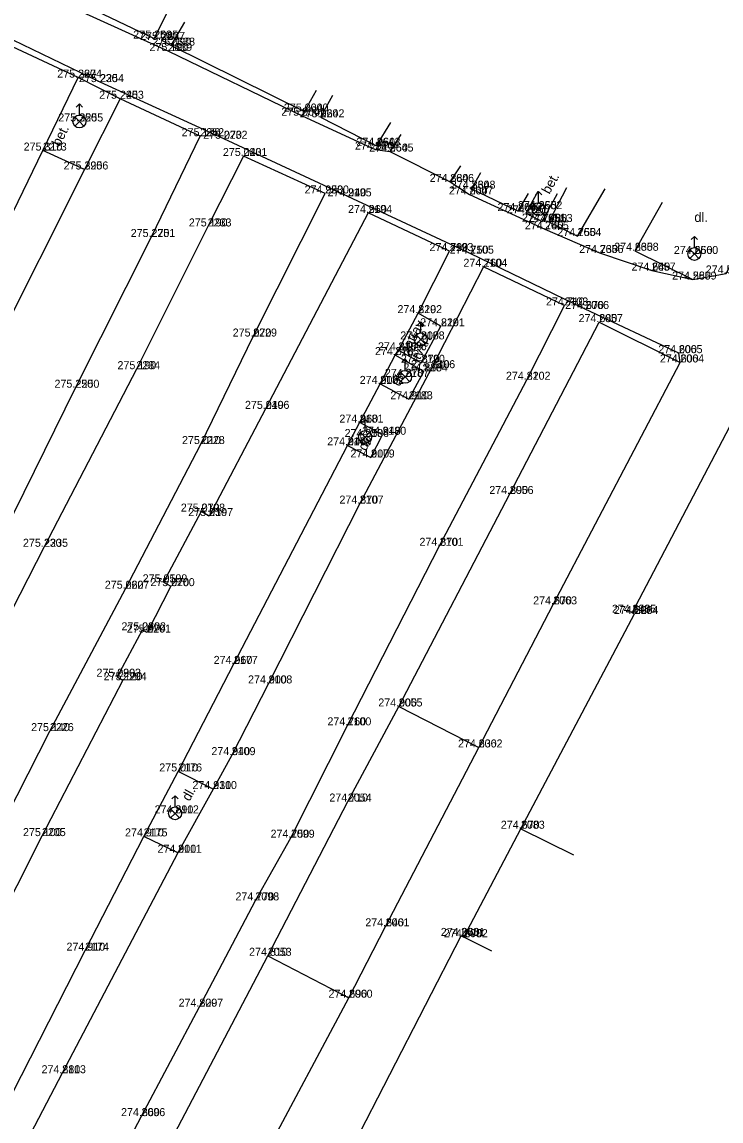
# Model space of a CAD drawing. Extents: x -776701 to -776081, y -974398 to -973771.
# Drawn here: x -776412.71 to -776390.87, y -974168.17 to -974133.83 of the extents above; entities that cross this region are included whole.
import ezdxf

# ---------------------------------------------------------------- set-up
doc = ezdxf.new("R2010")
doc.units = 0
for name, color, linetype in [('1 Body-bod', 7, 'Continuous'), ('10 Silnice-chodniky', 7, 'Continuous'), ('11 Rozhrani-nezpev zpev schody', 7, 'Continuous'), ('2 Body-cislo', 7, 'Continuous'), ('3 Body-vyska', 7, 'Continuous'), ('40 Popis-povrch', 7, 'Continuous'), ('58 Mobiliar', 7, 'Continuous'), ('7 Ploty', 7, 'Continuous')]:
    doc.layers.add(name, color=color, linetype=linetype)

msp = doc.modelspace()

# ---------------------------------------------------------------- linework, layer by layer
at = {"layer": '1 Body-bod'}
for p, q in [((-776408.58, -974134.35), (-776408.58, -974134.35)), ((-776408.36, -974134.39), (-776408.36, -974134.39)), ((-776408.05, -974134.57), (-776408.05, -974134.57)), ((-776408.14, -974134.74), (-776408.14, -974134.74)), ((-776410.96, -974135.57), (-776410.96, -974135.57)), ((-776410.27, -974135.71), (-776410.27, -974135.71)), ((-776409.65, -974136.23), (-776409.65, -974136.23)), ((-776403.88, -974136.63), (-776403.88, -974136.63)), ((-776410.92, -974136.94), (-776410.92, -974136.94)), ((-776403.96, -974136.76), (-776403.96, -974136.76)), ((-776403.38, -974136.81), (-776403.38, -974136.81)), ((-776407.14, -974137.4), (-776407.14, -974137.4)), ((-776406.41, -974137.48), (-776406.41, -974137.48)), ((-776401.63, -974137.7), (-776401.63, -974137.7)), ((-776412.06, -974137.85), (-776412.06, -974137.85)), ((-776405.79, -974138.02), (-776405.79, -974138.02)), ((-776401.68, -974137.82), (-776401.68, -974137.82)), ((-776401.22, -974137.88), (-776401.22, -974137.88)), ((-776410.76, -974138.44), (-776410.76, -974138.44)), ((-776399.33, -974138.83), (-776399.33, -974138.83)), ((-776398.66, -974139.04), (-776398.66, -974139.04)), ((-776403.24, -974139.19), (-776403.24, -974139.19)), ((-776402.53, -974139.28), (-776402.53, -974139.28)), ((-776398.73, -974139.22), (-776398.73, -974139.22)), ((-776397.21, -974139.74), (-776397.21, -974139.74)), ((-776396.57, -974139.68), (-776396.57, -974139.68)), ((-776401.89, -974139.8), (-776401.89, -974139.8)), ((-776396.97, -974139.81), (-776396.97, -974139.81)), ((-776396.46, -974140.07), (-776396.46, -974140.07)), ((-776396.25, -974140.08), (-776396.25, -974140.08)), ((-776406.91, -974140.22), (-776406.91, -974140.22)), ((-776396.37, -974140.31), (-776396.37, -974140.31)), ((-776408.67, -974140.55), (-776408.67, -974140.55)), ((-776395.35, -974140.52), (-776395.35, -974140.52)), ((-776399.35, -974140.99), (-776399.35, -974140.99)), ((-776398.71, -974141.07), (-776398.71, -974141.07)), ((-776394.66, -974141.05), (-776394.66, -974141.05)), ((-776393.56, -974140.98), (-776393.56, -974140.98)), ((-776391.7, -974141.08), (-776391.7, -974141.08)), ((-776398.29, -974141.48), (-776398.29, -974141.48)), ((-776393.03, -974141.6), (-776393.03, -974141.6)), ((-776391.75, -974141.88), (-776391.75, -974141.88)), ((-776395.76, -974142.69), (-776395.76, -974142.69)), ((-776395.11, -974142.8), (-776395.11, -974142.8)), ((-776400.33, -974142.93), (-776400.33, -974142.93)), ((-776399.62, -974143.34), (-776399.62, -974143.34)), ((-776394.68, -974143.21), (-776394.68, -974143.21)), ((-776405.49, -974143.66), (-776405.49, -974143.66)), ((-776400.25, -974143.75), (-776400.25, -974143.75)), ((-776400.95, -974144.09), (-776400.95, -974144.09)), ((-776392.19, -974144.18), (-776392.19, -974144.18)), ((-776401.05, -974144.24), (-776401.05, -974144.24)), ((-776400.24, -974144.48), (-776400.24, -974144.48)), ((-776392.14, -974144.47), (-776392.14, -974144.47)), ((-776409.14, -974144.68), (-776409.14, -974144.68)), ((-776400.74, -974144.92), (-776400.74, -974144.92)), ((-776400.15, -974144.75), (-776400.15, -974144.75)), ((-776399.92, -974144.65), (-776399.92, -974144.65)), ((-776411.04, -974145.26), (-776411.04, -974145.26)), ((-776401.52, -974145.14), (-776401.52, -974145.14)), ((-776396.94, -974145.01), (-776396.94, -974145.01)), ((-776405.1, -974145.92), (-776405.1, -974145.92)), ((-776400.62, -974145.62), (-776400.62, -974145.62)), ((-776402.16, -974146.35), (-776402.16, -974146.35)), ((-776401.99, -974146.8), (-776401.99, -974146.8)), ((-776401.45, -974146.73), (-776401.45, -974146.73)), ((-776407.12, -974147.02), (-776407.12, -974147.02)), ((-776402.54, -974147.06), (-776402.54, -974147.06)), ((-776401.81, -974147.44), (-776401.81, -974147.44)), ((-776397.47, -974148.58), (-776397.47, -974148.58)), ((-776402.16, -974148.88), (-776402.16, -974148.88)), ((-776407.11, -974149.13), (-776407.11, -974149.13)), ((-776406.86, -974149.27), (-776406.86, -974149.27)), ((-776412.02, -974150.23), (-776412.02, -974150.23)), ((-776399.66, -974150.2), (-776399.66, -974150.2)), ((-776408.29, -974151.34), (-776408.29, -974151.34)), ((-776409.48, -974151.54), (-776409.48, -974151.54)), ((-776408.06, -974151.46), (-776408.06, -974151.46)), ((-776396.11, -974152.03), (-776396.11, -974152.03)), ((-776393.64, -974152.29), (-776393.64, -974152.29)), ((-776393.57, -974152.33), (-776393.57, -974152.33)), ((-776408.96, -974152.84), (-776408.96, -974152.84)), ((-776408.8, -974152.91), (-776408.8, -974152.91)), ((-776406.09, -974153.89), (-776406.09, -974153.89)), ((-776409.74, -974154.29), (-776409.74, -974154.29)), ((-776409.56, -974154.4), (-776409.56, -974154.4)), ((-776405.01, -974154.5), (-776405.01, -974154.5)), ((-776400.94, -974155.22), (-776400.94, -974155.22)), ((-776402.54, -974155.81), (-776402.54, -974155.81)), ((-776411.84, -974155.99), (-776411.84, -974155.99)), ((-776398.44, -974156.5), (-776398.44, -974156.5)), ((-776406.16, -974156.74), (-776406.16, -974156.74)), ((-776407.83, -974157.25), (-776407.83, -974157.25)), ((-776406.74, -974157.8), (-776406.74, -974157.8)), ((-776402.53, -974158.19), (-776402.53, -974158.19)), ((-776407.93, -974158.56), (-776407.93, -974158.56)), ((-776412.09, -974159.27), (-776412.09, -974159.27)), ((-776408.91, -974159.28), (-776408.91, -974159.28)), ((-776404.31, -974159.32), (-776404.31, -974159.32)), ((-776397.12, -974159.04), (-776397.12, -974159.04)), ((-776407.84, -974159.79), (-776407.84, -974159.79)), ((-776405.42, -974161.28), (-776405.42, -974161.28)), ((-776401.35, -974162.09), (-776401.35, -974162.09)), ((-776398.99, -974162.39), (-776398.99, -974162.39)), ((-776398.9, -974162.43), (-776398.9, -974162.43)), ((-776410.74, -974162.85), (-776410.74, -974162.85)), ((-776405.03, -974163.01), (-776405.03, -974163.01)), ((-776402.5, -974164.32), (-776402.5, -974164.32)), ((-776407.17, -974164.6), (-776407.17, -974164.6)), ((-776411.46, -974166.68), (-776411.46, -974166.68)), ((-776408.98, -974168.02), (-776408.98, -974168.02))]:
    msp.add_line(p, q, dxfattribs=at)
at = {"layer": '10 Silnice-chodniky'}
for points in [[(-776398.71, -974141.07), (-776402.53, -974139.28), (-776406.41, -974137.48), (-776410.27, -974135.71), (-776414.21, -974133.82), (-776417.97, -974132.05), (-776421.8, -974130.27), (-776425.67, -974128.29), (-776429.7, -974126.41), (-776433.28, -974124.7), (-776436.96, -974123), (-776442.03, -974120.71), (-776442.3, -974120.97)], [(-776432.81, -974123), (-776431.7, -974123.4), (-776424.58, -974126.72), (-776422.72, -974127.77), (-776420.37, -974128.93), (-776419.95, -974129.14), (-776417.98, -974130.1), (-776417.46, -974130.35), (-776415.61, -974131.25), (-776413.4, -974132.37), (-776410.5, -974133.67), (-776408.14, -974134.74), (-776403.96, -974136.76), (-776401.68, -974137.82), (-776401.22, -974137.88)], [(-776409.65, -974136.23), (-776410.96, -974135.57)], [(-776410.76, -974138.44), (-776412.06, -974137.85)], [(-776399.33, -974138.83), (-776398.73, -974139.22), (-776396.37, -974140.31), (-776394.66, -974141.05), (-776393.03, -974141.6), (-776391.75, -974141.88)], [(-776396.597, -974139.131), (-776396.97, -974139.81), (-776396.46, -974140.07), (-776395.982, -974139.196)], [(-776392.14, -974144.47), (-776392.19, -974144.18), (-776395.11, -974142.8), (-776398.71, -974141.07)], [(-776400.95, -974144.09), (-776400.24, -974144.48), (-776399.62, -974143.34), (-776400.33, -974142.93)], [(-776401.52, -974145.14), (-776400.62, -974145.62), (-776400.15, -974144.75), (-776401.05, -974144.24)], [(-776402.54, -974147.06), (-776401.81, -974147.44), (-776401.45, -974146.73), (-776402.16, -974146.35)], [(-776397.12, -974159.04), (-776393.57, -974152.33)], [(-776406.74, -974157.8), (-776407.83, -974157.25)], [(-776407.84, -974159.79), (-776408.91, -974159.28)], [(-776400.67, -974169.754), (-776402.33, -974168.89), (-776398.99, -974162.39), (-776398.9, -974162.43)]]:
    msp.add_lwpolyline(points, dxfattribs=at)
at = {"layer": '11 Rozhrani-nezpev zpev schody'}
msp.add_lwpolyline([(-776392.71, -974139.472), (-776393.56, -974140.98), (-776391.75, -974141.88), (-776390.71, -974141.69), (-776389.38, -974139.19), (-776387.61, -974135.82), (-776388.963, -974135.076)], dxfattribs=at)
at = {"layer": '58 Mobiliar'}
for p, q in [((-776410.92, -974136.39), (-776411.02, -974136.49)), ((-776410.92, -974136.738), (-776410.92, -974136.39)), ((-776410.92, -974136.39), (-776410.82, -974136.49)), ((-776410.92, -974136.94), (-776411.062, -974136.797)), ((-776410.92, -974136.94), (-776411.062, -974137.083)), ((-776410.92, -974136.94), (-776410.777, -974136.797)), ((-776410.92, -974136.94), (-776410.92, -974136.94)), ((-776410.92, -974136.94), (-776410.777, -974137.083)), ((-776396.57, -974139.13), (-776396.67, -974139.23)), ((-776396.57, -974139.478), (-776396.57, -974139.13)), ((-776396.57, -974139.13), (-776396.47, -974139.23)), ((-776396.57, -974139.68), (-776396.713, -974139.537)), ((-776396.57, -974139.68), (-776396.713, -974139.823)), ((-776396.57, -974139.68), (-776396.427, -974139.537)), ((-776396.57, -974139.68), (-776396.57, -974139.68)), ((-776396.57, -974139.68), (-776396.427, -974139.823)), ((-776391.7, -974140.53), (-776391.8, -974140.63)), ((-776391.7, -974140.878), (-776391.7, -974140.53)), ((-776391.7, -974140.53), (-776391.6, -974140.63)), ((-776391.7, -974141.08), (-776391.843, -974140.938)), ((-776391.7, -974141.08), (-776391.843, -974141.223)), ((-776391.7, -974141.08), (-776391.557, -974140.938)), ((-776391.7, -974141.08), (-776391.7, -974141.08)), ((-776391.7, -974141.08), (-776391.557, -974141.223)), ((-776400.25, -974143.2), (-776400.35, -974143.3)), ((-776400.25, -974143.549), (-776400.25, -974143.2)), ((-776400.25, -974143.2), (-776400.15, -974143.3)), ((-776400.25, -974143.75), (-776400.392, -974143.608)), ((-776400.25, -974143.75), (-776400.392, -974143.893)), ((-776400.25, -974143.75), (-776400.108, -974143.608)), ((-776400.25, -974143.75), (-776400.25, -974143.75)), ((-776400.25, -974143.75), (-776400.108, -974143.893)), ((-776400.74, -974144.37), (-776400.84, -974144.47)), ((-776400.74, -974144.719), (-776400.74, -974144.37)), ((-776400.74, -974144.37), (-776400.64, -974144.47)), ((-776400.74, -974144.92), (-776400.883, -974144.777)), ((-776400.74, -974144.92), (-776400.883, -974145.062)), ((-776400.74, -974144.92), (-776400.598, -974144.777)), ((-776400.74, -974144.92), (-776400.74, -974144.92)), ((-776400.74, -974144.92), (-776400.598, -974145.062)), ((-776401.99, -974146.25), (-776402.09, -974146.35)), ((-776401.99, -974146.598), (-776401.99, -974146.25)), ((-776401.99, -974146.25), (-776401.89, -974146.35)), ((-776401.99, -974146.8), (-776402.133, -974146.657)), ((-776401.99, -974146.8), (-776402.133, -974146.943)), ((-776401.99, -974146.8), (-776401.848, -974146.657)), ((-776401.99, -974146.8), (-776401.99, -974146.8)), ((-776401.99, -974146.8), (-776401.848, -974146.943)), ((-776407.93, -974158.01), (-776408.03, -974158.11)), ((-776407.93, -974158.358), (-776407.93, -974158.01)), ((-776407.93, -974158.01), (-776407.83, -974158.11)), ((-776407.93, -974158.56), (-776408.073, -974158.417)), ((-776407.93, -974158.56), (-776408.073, -974158.703)), ((-776407.93, -974158.56), (-776407.787, -974158.417)), ((-776407.93, -974158.56), (-776407.93, -974158.56)), ((-776407.93, -974158.56), (-776407.787, -974158.703))]:
    msp.add_line(p, q, dxfattribs=at)
for centre in [(-776410.92, -974136.94), (-776396.57, -974139.68), (-776391.7, -974141.08), (-776400.25, -974143.75), (-776400.74, -974144.92), (-776401.99, -974146.8), (-776407.93, -974158.56)]:
    msp.add_circle(centre, 0.202, dxfattribs=at)
at = {"layer": '7 Ploty'}
for p, q in [((-776408.05, -974134.57), (-776407.62, -974133.839)), ((-776400.94, -974155.22), (-776398.44, -974156.5)), ((-776405.03, -974163.01), (-776402.5, -974164.32))]:
    msp.add_line(p, q, dxfattribs=at)
for points in [[(-776409.898, -974132.463), (-776410.4, -974133.48), (-776408.58, -974134.35), (-776408.099, -974133.401)], [(-776432.01, -974176.96), (-776430.15, -974174.43), (-776428.84, -974172.48), (-776426.21, -974167.13), (-776424.02, -974162.64), (-776420.72, -974155.89), (-776417.48, -974149.18), (-776414.84, -974143.58), (-776412.06, -974137.85), (-776410.96, -974135.57), (-776413.49, -974134.39), (-776415.66, -974138.85), (-776417.85, -974143.38), (-776420.08, -974148.01), (-776422.17, -974152.39), (-776424.4, -974156.87), (-776426.57, -974161.43), (-776428.76, -974165.89), (-776429.88, -974168.2), (-776431.18, -974170.86), (-776433.91, -974174.88), (-776432.01, -974176.96)], [(-776408.36, -974134.39), (-776408.05, -974134.57), (-776403.88, -974136.63), (-776403.514, -974135.965)], [(-776431.34, -974177.69), (-776430.36, -974178.74), (-776429.05, -974179.3), (-776425.05, -974173.32), (-776421.66, -974166.59), (-776420.59, -974164.45), (-776417.2, -974157.6), (-776414.58, -974152.44), (-776411.04, -974145.26), (-776408.67, -974140.55), (-776407.14, -974137.4), (-776409.65, -974136.23), (-776410.76, -974138.44), (-776413.59, -974144.07), (-776416.31, -974149.56), (-776419.81, -974156.48), (-776423.16, -974163.16), (-776425.35, -974167.56), (-776426.48, -974169.85), (-776427.57, -974172.05), (-776429.18, -974174.63), (-776431.34, -974177.69)], [(-776403.009, -974136.124), (-776403.38, -974136.81), (-776401.63, -974137.7), (-776401.186, -974136.974)], [(-776400.875, -974137.35), (-776401.22, -974137.88), (-776399.33, -974138.83), (-776398.998, -974138.324)], [(-776418.01, -974168.03), (-776415.29, -974162.66), (-776413.55, -974159.33), (-776411.84, -974155.99), (-776409.48, -974151.54), (-776407.12, -974147.02), (-776405.49, -974143.66), (-776403.24, -974139.19), (-776405.79, -974138.02), (-776406.91, -974140.22), (-776409.14, -974144.68), (-776412.02, -974150.23), (-776414.31, -974154.7), (-776417.77, -974161.35), (-776420.5, -974166.71), (-776418.01, -974168.03)], [(-776398.389, -974138.549), (-776398.66, -974139.04), (-776397.21, -974139.74), (-776396.881, -974139.19)], [(-776395.692, -974139.012), (-776396.25, -974140.08), (-776395.35, -974140.52), (-776394.486, -974139.042)], [(-776414.17, -974169.55), (-776410.74, -974162.85), (-776408.91, -974159.28), (-776407.83, -974157.25), (-776406.09, -974153.89), (-776402.54, -974147.06), (-776401.52, -974145.14), (-776401.05, -974144.24), (-776400.95, -974144.09), (-776400.33, -974142.93), (-776399.35, -974140.99), (-776401.89, -974139.8), (-776405.1, -974145.92), (-776406.86, -974149.27), (-776407.11, -974149.13), (-776408.29, -974151.34), (-776408.06, -974151.46), (-776408.8, -974152.91), (-776408.96, -974152.84), (-776409.74, -974154.29), (-776409.56, -974154.4), (-776412.09, -974159.27), (-776414.44, -974163.91)], [(-776413.04, -974175.78), (-776408.98, -974168.02), (-776407.17, -974164.6), (-776405.42, -974161.28), (-776404.31, -974159.32), (-776402.54, -974155.81), (-776399.66, -974150.2), (-776396.94, -974145.01), (-776395.76, -974142.69), (-776398.29, -974141.48), (-776399.92, -974144.65), (-776402.16, -974148.88), (-776405.01, -974154.5), (-776406.16, -974156.74), (-776406.74, -974157.8), (-776407.84, -974159.79), (-776411.46, -974166.68), (-776415.53, -974174.46)], [(-776410.02, -974178.63), (-776411.75, -974182.02), (-776414.07, -974185.17), (-776414.88, -974186.15), (-776415.02, -974186.06), (-776417.11, -974188.76), (-776419.58, -974186.86), (-776418.35, -974185.27), (-776418.07, -974185.5), (-776417.25, -974184.38), (-776417.17, -974184.42), (-776416.48, -974183.46), (-776415.65, -974182.42), (-776415.01, -974181.59), (-776414.32, -974180.57), (-776411.96, -974176.29), (-776407.95, -974168.57), (-776405.03, -974163.01), (-776402.53, -974158.19), (-776400.94, -974155.22), (-776397.47, -974148.58), (-776394.68, -974143.21), (-776392.14, -974144.47)], [(-776410.02, -974178.63), (-776408, -974174.76), (-776405.13, -974169.26), (-776402.5, -974164.32), (-776401.35, -974162.09), (-776398.44, -974156.5), (-776396.11, -974152.03), (-776392.14, -974144.47)], [(-776393.57, -974152.33), (-776393.64, -974152.29), (-776390.14, -974145.62)], [(-776398.025, -974162.863), (-776398.9, -974162.43), (-776397.12, -974159.04), (-776395.475, -974159.855)]]:
    msp.add_lwpolyline(points, dxfattribs=at)

# ---------------------------------------------------------------- texts
at = {"layer": '2 Body-cislo'}
for s, p in [('2635', (-776408.58, -974134.35)), ('2637', (-776408.36, -974134.39)), ('2639', (-776408.14, -974134.74)), ('2638', (-776408.05, -974134.57)), ('2274', (-776410.96, -974135.57)), ('2254', (-776410.27, -974135.71)), ('2253', (-776409.65, -974136.23)), ('2641', (-776403.96, -974136.76)), ('2640', (-776403.88, -974136.63)), ('2642', (-776403.38, -974136.81)), ('2255', (-776410.92, -974136.94)), ('2252', (-776407.14, -974137.4)), ('2232', (-776406.41, -974137.48)), ('2273', (-776412.06, -974137.85)), ('2644', (-776401.68, -974137.82)), ('2643', (-776401.63, -974137.7)), ('2645', (-776401.22, -974137.88)), ('2231', (-776405.79, -974138.02)), ('2256', (-776410.76, -974138.44)), ('2646', (-776399.33, -974138.83)), ('2230', (-776403.24, -974139.19)), ('2195', (-776402.53, -974139.28)), ('2647', (-776398.73, -974139.22)), ('2648', (-776398.66, -974139.04)), ('2652', (-776396.57, -974139.68)), ('2194', (-776401.89, -974139.8)), ('2649', (-776397.21, -974139.74)), ('2650', (-776396.97, -974139.81)), ('2233', (-776406.91, -974140.22)), ('2651', (-776396.46, -974140.07)), ('2655', (-776396.37, -974140.31)), ('2653', (-776396.25, -974140.08)), ('2251', (-776408.67, -974140.55)), ('2654', (-776395.35, -974140.52)), ('2193', (-776399.35, -974140.99)), ('2656', (-776394.66, -974141.05)), ('2658', (-776393.56, -974140.98)), ('2105', (-776398.71, -974141.07)), ('2660', (-776391.7, -974141.08)), ('2104', (-776398.29, -974141.48)), ('2657', (-776393.03, -974141.6)), ('2659', (-776391.75, -974141.88)), ('2103', (-776395.76, -974142.69)), ('2192', (-776400.33, -974142.93)), ('2066', (-776395.11, -974142.8)), ('2191', (-776399.62, -974143.34)), ('2057', (-776394.68, -974143.21)), ('2229', (-776405.49, -974143.66)), ('2188', (-776400.25, -974143.75)), ('2189', (-776400.95, -974144.09)), ('2185', (-776401.05, -974144.24)), ('2190', (-776400.24, -974144.48)), ('2065', (-776392.19, -974144.18)), ('2064', (-776392.14, -974144.47)), ('2234', (-776409.14, -974144.68)), ('2184', (-776400.15, -974144.75)), ('2106', (-776399.92, -974144.65)), ('2182', (-776401.52, -974145.14)), ('2187', (-776400.74, -974144.92)), ('2102', (-776396.94, -974145.01)), ('2250', (-776411.04, -974145.26)), ('2183', (-776400.62, -974145.62)), ('2196', (-776405.1, -974145.92)), ('2181', (-776402.16, -974146.35)), ('2186', (-776401.99, -974146.8)), ('2180', (-776401.45, -974146.73)), ('2228', (-776407.12, -974147.02)), ('2178', (-776402.54, -974147.06)), ('2179', (-776401.81, -974147.44)), ('2056', (-776397.47, -974148.58)), ('2107', (-776402.16, -974148.88)), ('2198', (-776407.11, -974149.13)), ('2197', (-776406.86, -974149.27)), ('2235', (-776412.02, -974150.23)), ('2101', (-776399.66, -974150.2)), ('2199', (-776408.29, -974151.34)), ('2227', (-776409.48, -974151.54)), ('2200', (-776408.06, -974151.46)), ('2063', (-776396.11, -974152.03)), ('2085', (-776393.64, -974152.29)), ('2084', (-776393.57, -974152.33)), ('2202', (-776408.96, -974152.84)), ('2201', (-776408.8, -974152.91)), ('2177', (-776406.09, -974153.89)), ('2203', (-776409.74, -974154.29)), ('2204', (-776409.56, -974154.4)), ('2108', (-776405.01, -974154.5)), ('2055', (-776400.94, -974155.22)), ('2100', (-776402.54, -974155.81)), ('2226', (-776411.84, -974155.99)), ('2062', (-776398.44, -974156.5)), ('2109', (-776406.16, -974156.74)), ('2176', (-776407.83, -974157.25)), ('2110', (-776406.74, -974157.8)), ('2054', (-776402.53, -974158.19)), ('2112', (-776407.93, -974158.56)), ('2083', (-776397.12, -974159.04)), ('2205', (-776412.09, -974159.27)), ('2175', (-776408.91, -974159.28)), ('2099', (-776404.31, -974159.32)), ('2111', (-776407.84, -974159.79)), ('2098', (-776405.42, -974161.28)), ('2061', (-776401.35, -974162.09)), ('2081', (-776398.99, -974162.39)), ('2082', (-776398.9, -974162.43)), ('2174', (-776410.74, -974162.85)), ('2053', (-776405.03, -974163.01)), ('2060', (-776402.5, -974164.32)), ('2097', (-776407.17, -974164.6)), ('2113', (-776411.46, -974166.68)), ('2096', (-776408.98, -974168.02))]:
    msp.add_text(s, height=0.25, dxfattribs=at).set_placement(p)
at = {"layer": '3 Body-vyska'}
for s, p in [('275.250', (-776409.238, -974134.35)), ('275.220', (-776409.022, -974134.39)), ('275.190', (-776408.729, -974134.74)), ('275.190', (-776408.639, -974134.57)), ('275.260', (-776411.612, -974135.57)), ('275.230', (-776410.934, -974135.71)), ('275.240', (-776410.302, -974136.23)), ('275.000', (-776404.609, -974136.76)), ('275.000', (-776404.529, -974136.63)), ('275.020', (-776404.035, -974136.81)), ('275.350', (-776411.58, -974136.94)), ('275.170', (-776407.724, -974137.4)), ('275.070', (-776407.049, -974137.48)), ('275.310', (-776412.662, -974137.85)), ('274.970', (-776402.308, -974137.82)), ('274.960', (-776402.264, -974137.7)), ('274.950', (-776401.861, -974137.88)), ('275.040', (-776406.435, -974138.02)), ('275.390', (-776411.413, -974138.44)), ('274.880', (-776399.972, -974138.83)), ('274.950', (-776403.881, -974139.19)), ('274.940', (-776403.164, -974139.28)), ('274.800', (-776399.372, -974139.22)), ('274.830', (-776399.311, -974139.04)), ('274.850', (-776397.215, -974139.68)), ('274.960', (-776402.524, -974139.8)), ('274.800', (-776397.852, -974139.74)), ('274.810', (-776397.557, -974139.81)), ('275.190', (-776407.499, -974140.22)), ('274.790', (-776397.088, -974140.07)), ('274.740', (-776396.998, -974140.31)), ('274.780', (-776396.882, -974140.08)), ('275.270', (-776409.316, -974140.55)), ('274.750', (-776395.985, -974140.52)), ('274.790', (-776399.978, -974140.99)), ('274.730', (-776395.301, -974141.05)), ('274.630', (-776394.207, -974140.98)), ('274.750', (-776399.345, -974141.07)), ('274.650', (-776392.341, -974141.08)), ('274.760', (-776398.918, -974141.48)), ('274.640', (-776393.664, -974141.6)), ('274.570', (-776391.345, -974141.69)), ('274.580', (-776392.395, -974141.88)), ('274.710', (-776396.337, -974142.69)), ('274.820', (-776400.979, -974142.93)), ('274.670', (-776395.738, -974142.8)), ('274.820', (-776400.269, -974143.34)), ('274.680', (-776395.318, -974143.21)), ('275.070', (-776406.129, -974143.66)), ('274.800', (-776400.892, -974143.75)), ('274.840', (-776401.588, -974144.09)), ('274.870', (-776401.682, -974144.24)), ('274.870', (-776400.872, -974144.48)), ('274.600', (-776392.828, -974144.18)), ('274.600', (-776392.778, -974144.47)), ('275.190', (-776409.729, -974144.68)), ('274.880', (-776400.792, -974144.75)), ('274.840', (-776400.558, -974144.65)), ('274.900', (-776402.158, -974145.14)), ('274.870', (-776401.372, -974144.92)), ('274.820', (-776397.589, -974145.01)), ('275.250', (-776411.698, -974145.26)), ('274.910', (-776401.203, -974145.62)), ('275.040', (-776405.745, -974145.92)), ('274.960', (-776402.794, -974146.35)), ('274.950', (-776402.631, -974146.8)), ('274.940', (-776402.084, -974146.73)), ('275.010', (-776407.713, -974147.02)), ('274.940', (-776403.174, -974147.06)), ('274.900', (-776402.448, -974147.44)), ('274.890', (-776398.108, -974148.58)), ('274.870', (-776402.792, -974148.88)), ('275.070', (-776407.749, -974149.13)), ('275.030', (-776407.517, -974149.27)), ('275.230', (-776412.684, -974150.23)), ('274.870', (-776400.292, -974150.2)), ('275.050', (-776408.942, -974151.34)), ('275.060', (-776410.125, -974151.54)), ('275.070', (-776408.699, -974151.46)), ('274.670', (-776396.738, -974152.03)), ('274.640', (-776394.274, -974152.29)), ('274.620', (-776394.215, -974152.33)), ('275.060', (-776409.605, -974152.84)), ('275.070', (-776409.439, -974152.91)), ('274.960', (-776406.724, -974153.89)), ('275.090', (-776410.385, -974154.29)), ('275.120', (-776410.16, -974154.4)), ('274.900', (-776405.648, -974154.5)), ('274.900', (-776401.578, -974155.22)), ('274.760', (-776403.168, -974155.81)), ('275.140', (-776412.429, -974155.99)), ('274.630', (-776399.087, -974156.5)), ('274.940', (-776406.794, -974156.74)), ('275.010', (-776408.423, -974157.25)), ('274.930', (-776407.387, -974157.8)), ('274.710', (-776403.107, -974158.19)), ('274.890', (-776408.568, -974158.56)), ('274.670', (-776397.748, -974159.04)), ('275.100', (-776412.683, -974159.27)), ('274.910', (-776409.493, -974159.28)), ('274.750', (-776404.945, -974159.32)), ('274.900', (-776408.478, -974159.79)), ('274.770', (-776406.042, -974161.28)), ('274.640', (-776401.984, -974162.09)), ('274.660', (-776399.624, -974162.39)), ('274.670', (-776399.528, -974162.43)), ('274.910', (-776411.323, -974162.85)), ('274.810', (-776405.617, -974163.01)), ('274.690', (-776403.134, -974164.32)), ('274.820', (-776407.819, -974164.6)), ('274.880', (-776412.102, -974166.68)), ('274.860', (-776409.618, -974168.02))]:
    msp.add_text(s, height=0.25, dxfattribs=at).set_placement(p)
at = {"layer": '40 Popis-povrch'}
for s, rotation, p in [('bet.', 63.3313, (-776411.532, -974137.737)), ('bet.', 61.3392, (-776396.23, -974139.231)), ('zatrav.', 61.8763, (-776400.638, -974144.219)), ('tvar.', 61.8763, (-776400.285, -974144.407)), ('dl.', 61.6208, (-776400.917, -974145.237)), ('dl.', 63.1131, (-776401.964, -974147.254)), ('dl.', 61.0678, (-776407.478, -974158.201))]:
    msp.add_text(s, height=0.3, rotation=rotation, dxfattribs=at).set_placement(p)
msp.add_text('dl.', height=0.3, dxfattribs=at).set_placement((-776391.7, -974140.08))

doc.saveas('drawing.dxf')
